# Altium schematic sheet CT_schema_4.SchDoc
size 207 x 170 mm
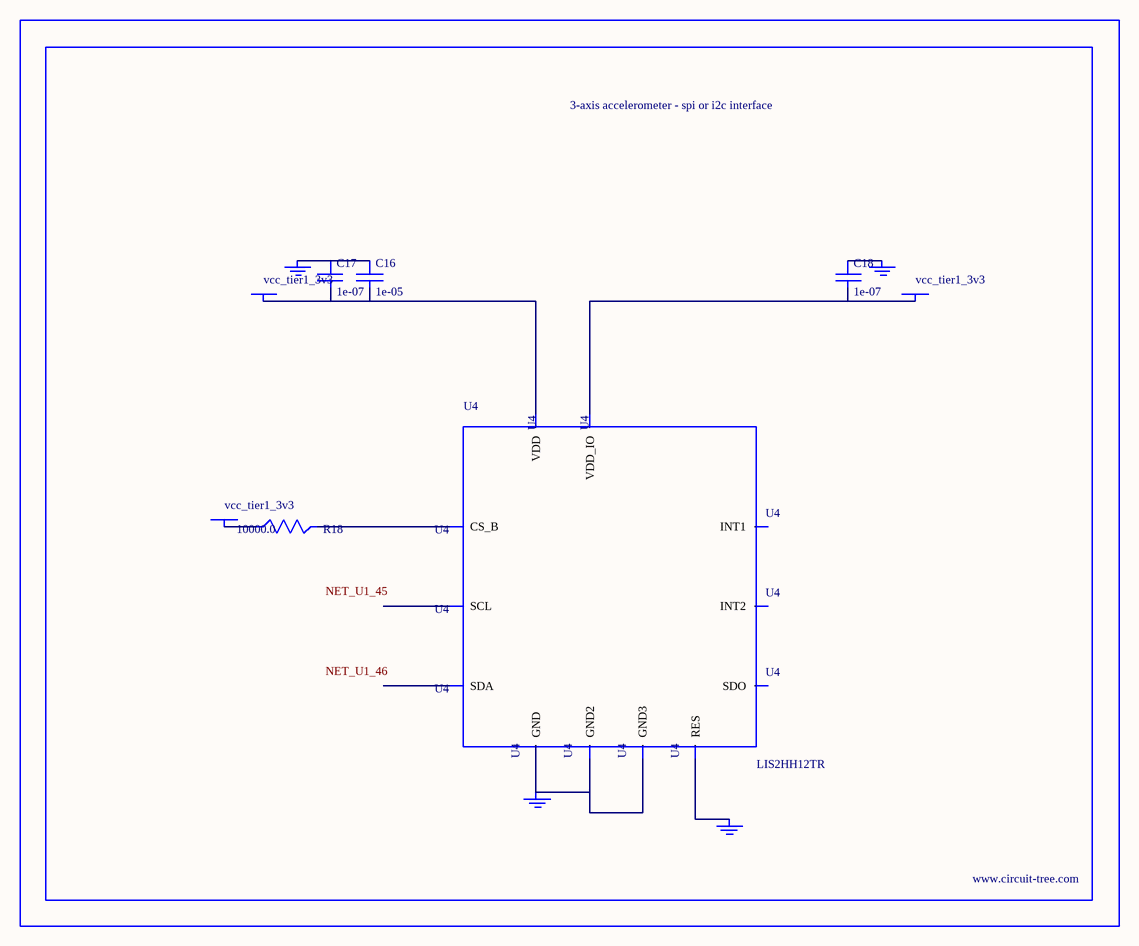
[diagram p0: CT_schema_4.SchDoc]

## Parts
BORDER3  (no value)
C16  1e-05  [C0805]
C17  1e-07  [C0402]
C18  1e-07  [C0402]
GND_INSTANCE_3_0  (no value)
GND_INSTANCE_3_1  (no value)
GND_INSTANCE_3_2  (no value)
GND_INSTANCE_3_3  (no value)
POWER_INSTANCE_3_0  vcc_tier1_3v3
POWER_INSTANCE_3_1  vcc_tier1_3v3
POWER_INSTANCE_3_2  vcc_tier1_3v3
R18  10000.0  [R0603]
U4  LIS2HH12TR  [LGA-12]

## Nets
NetC16_1: C16.1 C17.1 GND_INSTANCE_3_1.0(GND)
NetC16_2: C16.2 C17.2 POWER_INSTANCE_3_1.0(PWR) U4.9(VDD)
NetC18_1: C18.1 GND_INSTANCE_3_2.0(GND)
NetC18_2: C18.2 POWER_INSTANCE_3_2.0(PWR) U4.10(VDD_IO)
NetGND_INSTANCE_3_0_0: GND_INSTANCE_3_0.0(GND) U4.5(RES)
NetGND_INSTANCE_3_3_0: GND_INSTANCE_3_3.0(GND) U4.6(GND) U4.7(GND2) U4.8(GND3)
NetPOWER_INSTANCE_3_0_0: POWER_INSTANCE_3_0.0(PWR) R18.1
NetR18_2: R18.2 U4.2(CS_B)

Not connected (* = marked no-connect by the designer): U4 1(SCL) 3(SDO) 4(SDA) 11(INT2) 12(INT1)

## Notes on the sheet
- Labels drawn without touching a wire or pin: NET_U1_45, NET_U1_46

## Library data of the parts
BORDER3 = BORDER_PAGE3
C16 = C0805C106K8RACTU
C17 C18 = C0402C104K3RACTU
GND_INSTANCE_3_0-GND_INSTANCE_3_3 = GND
POWER_INSTANCE_3_0-POWER_INSTANCE_3_2 = PWR
R18 = RC0603JR-0710KL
